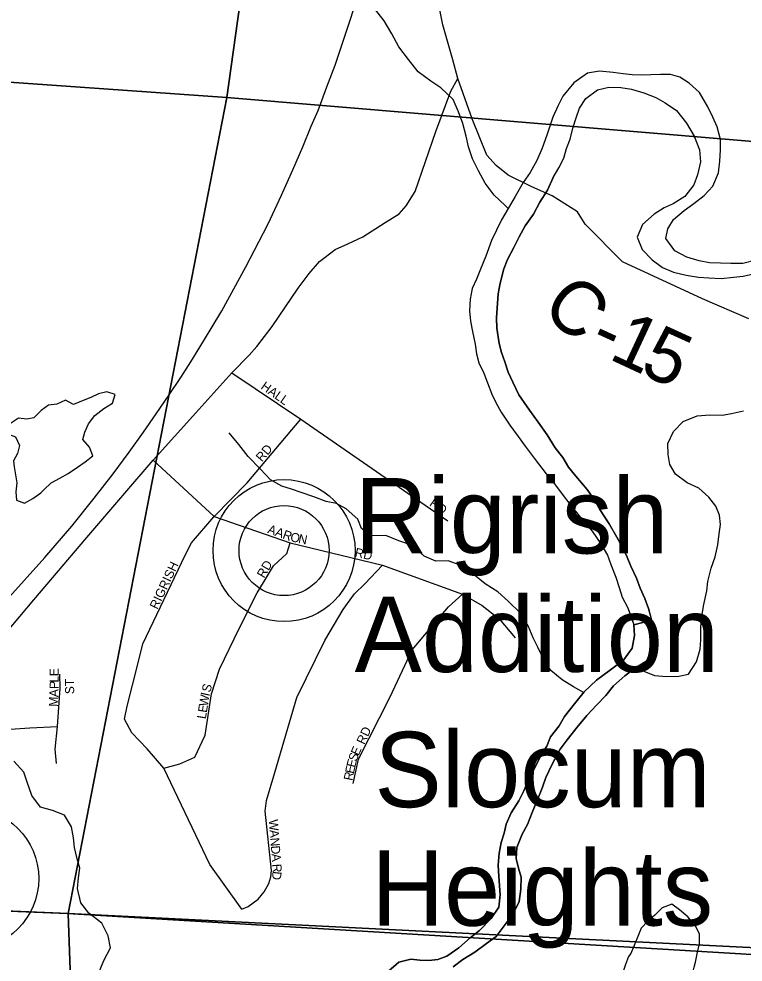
# Model space of a CAD drawing. Extents: x 1624196 to 2029251, y 146837 to 440034.
# Drawn here: x 1865984 to 1869991, y 281306 to 286524 of the extents above; entities that cross this region are included whole.
import ezdxf

# ---------------------------------------------------------------- set-up
doc = ezdxf.new("R2010")
doc.units = 0
for name, color, linetype in [('GM_X_County_Road', 7, 'Continuous'), ('GM_X_County_Road_Text', 7, 'Continuous'), ('GM_X_Major_River', 7, 'Continuous'), ('GM_X_Minor_Lake', 7, 'Continuous'), ('GM_X_Minor_River', 7, 'Continuous'), ('GM_X_Rail_Line', 7, 'Continuous'), ('GM_X_Section', 7, 'Continuous'), ('GM_X_State_Route', 7, 'Continuous'), ('GM_X_Township', 7, 'Continuous'), ('GM_X_Township_Subdivision', 7, 'Continuous'), ('GM_X_Township_Subdivision_Text', 7, 'Continuous'), ('GM_X_Unincorporated', 7, 'Continuous'), ('GM_X_Unincorporated_Location', 7, 'Continuous'), ('GM_X_Unincorporated_Text', 7, 'Continuous')]:
    doc.layers.add(name, color=color, linetype=linetype)

msp = doc.modelspace()

# ---------------------------------------------------------------- linework, layer by layer
at = {"layer": 'GM_X_County_Road'}
msp.add_lwpolyline([(1870021.8, 284865), (1869766.6, 284976), (1869323.4, 285180.8), (1869117.6, 285388.1), (1869074.6, 285456.5), (1868934.4, 285545.2), (1868821, 285594.7), (1868691.1, 285658.7), (1868625.1, 285712.3), (1868573.5, 285770.1), (1868492.6, 285971.2), (1868413.2, 286195)], dxfattribs=at)
at = {"layer": 'GM_X_Major_River'}
for p, q in [((1869485.1, 283197.2), (1869386.3, 283172.7)), ((1869386.3, 283172.7), (1869485.1, 283197.2))]:
    msp.add_line(p, q, dxfattribs=at)
for points in [[(1870060.6, 285189), (1869988.4, 285171.5), (1869922.3, 285170), (1869866.2, 285172.4), (1869804.2, 285174.9), (1869748.2, 285185.3), (1869678.3, 285205.8), (1869612.4, 285240.4), (1869562.9, 285308.8), (1869573.2, 285362.8), (1869605.6, 285414.7), (1869664, 285464.3), (1869718.3, 285501.9), (1869774.7, 285547.6), (1869823.1, 285599.3), (1869853.6, 285673.1), (1869862.1, 285737.2), (1869864.5, 285799.2), (1869864.9, 285857.3), (1869847.4, 285927.5), (1869823.7, 285979.8), (1869796.1, 286038.1), (1869748.5, 286116.5), (1869692.8, 286169), (1869641, 286201.4), (1869589.1, 286215.8), (1869533, 286216.3), (1869480.9, 286214.6), (1869430.9, 286213), (1869376.8, 286215.4), (1869326.8, 286219.8), (1869270.8, 286228.2), (1869196.8, 286234.8), (1869130.6, 286223.3), (1869054.2, 286169.8), (1868993.6, 286096.1), (1868967.2, 286044.2), (1868938.8, 285980.4), (1868904.1, 285880.5), (1868879.6, 285808.6), (1868849.1, 285740.7), (1868812.6, 285674.9), (1868774.1, 285619.1), (1868729.6, 285541.4), (1868691.1, 285475.6), (1868654.6, 285411.8), (1868626.2, 285355.9), (1868597.8, 285298), (1868567.2, 285212.1), (1868538.6, 285140.3), (1868516.2, 285084.3), (1868491.9, 285032.5), (1868481.5, 284974.5), (1868477, 284908.4), (1868482.6, 284852.3), (1868494.3, 284794.1), (1868507.8, 284723.9), (1868515.4, 284671.8), (1868529.1, 284621.6), (1868556.7, 284563.4), (1868576.4, 284511.1), (1868600, 284448.9), (1868623.7, 284398.6), (1868651.4, 284348.4), (1868700.9, 284275.9), (1868746.6, 284213.5), (1868784.2, 284161.1), (1868833.8, 284094.7), (1868901.3, 284008.1), (1868947, 283951.7), (1868994.6, 283887.2), (1869044.2, 283822.8), (1869107.8, 283746.2), (1869155.4, 283689.8), (1869203, 283619.3), (1869240.6, 283557), (1869258.3, 283506.8), (1869285.8, 283436.5), (1869305.5, 283378.2), (1869321.1, 283326), (1869352.4, 283266.6), (1869386.3, 283172.7)], [(1870060.6, 285189), (1869988.4, 285171.5), (1869922.3, 285170), (1869866.2, 285172.4), (1869804.2, 285174.9), (1869748.2, 285185.3), (1869678.3, 285205.8), (1869612.4, 285240.4), (1869562.9, 285308.8), (1869573.2, 285362.8), (1869605.6, 285414.7), (1869664, 285464.3), (1869718.3, 285501.9), (1869774.7, 285547.6), (1869823.1, 285599.3), (1869853.6, 285673.1), (1869862.1, 285737.2), (1869864.5, 285799.2), (1869864.9, 285857.3), (1869847.4, 285927.5), (1869823.7, 285979.8), (1869796.1, 286038.1), (1869748.5, 286116.5), (1869692.8, 286169), (1869641, 286201.4), (1869589.1, 286215.8), (1869533, 286216.3), (1869480.9, 286214.6), (1869430.9, 286213), (1869376.8, 286215.4), (1869326.8, 286219.8), (1869270.8, 286228.2), (1869196.8, 286234.8), (1869130.6, 286223.3), (1869054.2, 286169.8), (1868993.6, 286096.1), (1868967.2, 286044.2), (1868938.8, 285980.4), (1868904.1, 285880.5), (1868879.6, 285808.6), (1868849.1, 285740.7), (1868812.6, 285674.9), (1868774.1, 285619.1), (1868729.6, 285541.4), (1868691.1, 285475.6), (1868654.6, 285411.8), (1868626.2, 285355.9), (1868597.8, 285298), (1868567.2, 285212.1), (1868538.6, 285140.3), (1868516.2, 285084.3), (1868491.9, 285032.5), (1868481.5, 284974.5), (1868477, 284908.4), (1868482.6, 284852.3), (1868494.3, 284794.1), (1868507.8, 284723.9), (1868515.4, 284671.8), (1868529.1, 284621.6), (1868556.7, 284563.4), (1868576.4, 284511.1), (1868600, 284448.9), (1868623.7, 284398.6), (1868651.4, 284348.4), (1868700.9, 284275.9), (1868746.6, 284213.5), (1868784.2, 284161.1), (1868833.8, 284094.7), (1868901.3, 284008.1), (1868947, 283951.7), (1868994.6, 283887.2), (1869044.2, 283822.8), (1869107.8, 283746.2), (1869155.4, 283689.8), (1869203, 283619.3), (1869240.6, 283557), (1869258.3, 283506.8), (1869285.8, 283436.5), (1869305.5, 283378.2), (1869321.1, 283326), (1869352.4, 283266.6), (1869386.3, 283173.4)], [(1868940.5, 285645.9), (1868970.9, 285699.8), (1868999.3, 285753.6), (1869013.7, 285807.6), (1869034.1, 285859.5), (1869048.5, 285919.5), (1869066.9, 285977.4), (1869085.3, 286029.4), (1869119.7, 286083.2), (1869184.1, 286130.8), (1869248.2, 286146.3), (1869314.3, 286143.8), (1869372.3, 286135.3), (1869442.2, 286114.8), (1869508.1, 286088.3), (1869560, 286059.8), (1869621.7, 286017.3), (1869677.3, 285946.8), (1869718.9, 285874.4), (1869748.4, 285800.1), (1869753.9, 285734), (1869737.4, 285662), (1869717, 285606.1), (1869668.6, 285542.4), (1869604.2, 285500.8), (1869554, 285479.1), (1869497.7, 285443.5), (1869433.2, 285385.9), (1869404.7, 285316), (1869432.3, 285247.7), (1869488, 285191.2), (1869543.7, 285148.8), (1869605.6, 285122.3), (1869675.6, 285105.7), (1869743.6, 285095.2), (1869801.6, 285090.8), (1869869.7, 285088.3), (1869937.8, 285095.8), (1869989.9, 285101.4), (1870072.1, 285118.8)], [(1868940.5, 285645.9), (1868908, 285576.1), (1868865.5, 285510.3), (1868831, 285444.5), (1868784.5, 285378.7), (1868752.1, 285318.9), (1868721.6, 285259), (1868687.2, 285193.2), (1868666.8, 285141.3), (1868646.2, 285061.3), (1868635.8, 285003.3), (1868629.3, 284923.3), (1868626.9, 284871.2), (1868628.5, 284813.2), (1868642, 284729), (1868653.6, 284678.8), (1868673.3, 284626.6), (1868690.9, 284570.4), (1868716.6, 284514.1), (1868750.1, 284443.8), (1868809.6, 284359.2), (1868857.2, 284292.8), (1868906.8, 284222.3), (1868950.4, 284151.9), (1868994, 284097.5), (1869023.7, 284045.2), (1869065.4, 283994.8), (1869127, 283920.3), (1869170.6, 283859.9), (1869198.3, 283809.6), (1869249.8, 283731.1), (1869291.3, 283656.7), (1869321, 283604.4), (1869348.6, 283546.1), (1869370.3, 283495.9), (1869399.9, 283429.6), (1869421.6, 283375.4), (1869447.2, 283317.1), (1869466.8, 283262.9), (1869486.4, 283192.6), (1869500, 283142.5), (1869511.7, 283086.3), (1869509.3, 283030.2), (1869458.8, 282972.5), (1869390.5, 282931), (1869336.1, 282889.4), (1869273.7, 282833.8), (1869231.3, 282782), (1869178.9, 282728.3), (1869126.4, 282670.6), (1869072, 282607), (1869017.4, 282535.3), (1868979, 282483.5), (1868934.4, 282401.7), (1868899.9, 282327.9), (1868881.5, 282274), (1868859.1, 282218), (1868824.5, 282134.2), (1868798, 282068.3), (1868767.6, 282014.5), (1868739.1, 281940.6), (1868734.7, 281880.5), (1868748.3, 281826.3), (1868762, 281776.2), (1868761.5, 281710.1), (1868751.1, 281642.1), (1868718.6, 281574.2), (1868664, 281500.6), (1868623.6, 281448.8), (1868571.3, 281409.1), (1868506.9, 281361.5), (1868440.6, 281320), (1868386.2, 281280.3)], [(1869485.1, 283197.2), (1869466.8, 283262.9), (1869447.2, 283317.1), (1869421.6, 283375.4), (1869399.9, 283429.6), (1869370.3, 283495.9), (1869348.6, 283546.1), (1869321, 283604.4), (1869291.3, 283656.7), (1869249.8, 283731.1), (1869198.3, 283809.6), (1869170.6, 283859.9), (1869127, 283920.3), (1869065.4, 283994.8), (1869023.7, 284045.2), (1868994, 284097.5), (1868950.4, 284151.9), (1868906.8, 284222.3), (1868857.2, 284292.8), (1868809.6, 284359.2), (1868750.1, 284443.8), (1868716.6, 284514.1), (1868690.9, 284570.4), (1868673.3, 284626.6), (1868653.6, 284678.8), (1868642, 284729), (1868628.5, 284813.2), (1868626.9, 284871.2), (1868629.3, 284923.3), (1868635.8, 285003.3), (1868646.2, 285061.3), (1868666.8, 285141.3), (1868687.2, 285193.2), (1868721.6, 285259), (1868752.1, 285318.9), (1868784.5, 285378.7), (1868831, 285444.5), (1868865.5, 285510.3), (1868908, 285576.1), (1868940.5, 285645.9)], [(1868029.2, 281256.7), (1868085.5, 281306.6), (1868151.7, 281322.3), (1868201.8, 281318.1), (1868251.8, 281315.8), (1868301.9, 281321.6), (1868352.1, 281339.5), (1868418.4, 281385.3), (1868480.7, 281441.1), (1868533, 281481), (1868597.4, 281546.8), (1868639.7, 281610.8), (1868646, 281678.9), (1868638.5, 281779.2), (1868634.8, 281843.4), (1868641.1, 281909.5), (1868651.3, 281967.6), (1868669.6, 282019.7), (1868679.8, 282069.8), (1868708.1, 282131.8), (1868750.5, 282197.8), (1868776.8, 282253.8), (1868807.1, 282323.8), (1868837.4, 282377.8), (1868871.8, 282449.8), (1868904.1, 282501.8), (1868924.3, 282551.8), (1868972.7, 282613.8), (1869003, 282665.8), (1869057.3, 282735.7), (1869111.7, 282801.6), (1869180.1, 282865.5), (1869256.5, 282923.2), (1869328.8, 282977), (1869377.2, 283043), (1869389.5, 283113.1), (1869386.3, 283173.4)], [(1869386.3, 283172.7), (1869389.5, 283113.1), (1869377.2, 283043), (1869328.8, 282977), (1869256.5, 282923.2), (1869180.1, 282865.5), (1869111.7, 282801.6), (1869057.3, 282735.7), (1869003, 282665.8), (1868972.7, 282613.8), (1868924.3, 282551.8), (1868904.1, 282501.8), (1868871.8, 282449.8), (1868837.4, 282377.8), (1868807.1, 282323.8), (1868776.8, 282253.8), (1868750.5, 282197.8), (1868708.1, 282131.8), (1868679.8, 282069.8), (1868669.6, 282019.7), (1868651.3, 281967.6), (1868641.1, 281909.5), (1868634.8, 281843.4), (1868638.5, 281779.2), (1868646, 281678.9), (1868639.7, 281610.8), (1868597.4, 281546.8), (1868533, 281481), (1868480.7, 281441.1), (1868418.4, 281385.3), (1868352.1, 281339.5), (1868301.9, 281321.6), (1868251.8, 281315.8), (1868201.8, 281318.1), (1868151.7, 281322.3), (1868085.5, 281306.6), (1868029.2, 281256.7)], [(1868386.2, 281280.3), (1868440.6, 281320), (1868506.9, 281361.5), (1868571.3, 281409.1), (1868623.6, 281448.8), (1868664, 281500.6), (1868718.6, 281574.2), (1868751.1, 281642.1), (1868761.5, 281710.1), (1868762, 281776.2), (1868748.3, 281826.3), (1868734.7, 281880.5), (1868739.1, 281940.6), (1868767.6, 282014.5), (1868798, 282068.3), (1868824.5, 282134.2), (1868859.1, 282218), (1868881.5, 282274), (1868899.9, 282327.9), (1868934.4, 282401.7), (1868979, 282483.5), (1869017.4, 282535.3), (1869072, 282607), (1869126.4, 282670.6), (1869178.9, 282728.3), (1869231.3, 282782), (1869273.7, 282833.8), (1869336.1, 282889.4), (1869390.5, 282931), (1869458.8, 282972.5), (1869509.3, 283030.2), (1869511.7, 283086.3), (1869500, 283142.5), (1869485.1, 283197.2)]]:
    msp.add_lwpolyline(points, dxfattribs=at)
at = {"layer": 'GM_X_Minor_Lake'}
for points in [[(1866122.1, 283918.3), (1866162.3, 283958.2), (1866210.5, 283984.1), (1866256.7, 284009.9), (1866309, 284043.8), (1866351.1, 284073.7), (1866393.4, 284107.5), (1866375.5, 284155.8), (1866337.7, 284198), (1866349.9, 284238.1), (1866370.1, 284284.1), (1866404.4, 284330.1), (1866454.6, 284367.9), (1866502.8, 284397.8), (1866517, 284445.8), (1866471, 284460.1), (1866424.9, 284450.3), (1866382.8, 284430.4), (1866330.6, 284408.6), (1866286.4, 284390.8), (1866242.5, 284415), (1866194.3, 284393.2), (1866148.2, 284387.4), (1866108, 284357.5), (1866087, 284336.6)], [(1866087, 284336.6), (1866067.8, 284317.6), (1866027.7, 284309.8), (1865981.7, 284316), (1865933.4, 284282.1), (1865913.2, 284232.1), (1865965.2, 284211.8), (1865987, 284163.6), (1865976.8, 284119.5), (1865954.6, 284079.5), (1865958.4, 284045.4), (1865974, 283957.1), (1865967.8, 283907), (1865971.6, 283860.9), (1866015.6, 283844.6), (1866061.8, 283870.5), (1866106, 283902.4), (1866122.1, 283918.3)], [(1869720.3, 281279.2), (1869728, 281307), (1869738.3, 281361.1), (1869748.5, 281407.1), (1869748.8, 281461.3), (1869726.9, 281507.5), (1869685.1, 281557.8), (1869639.2, 281596.1), (1869595.3, 281626.4), (1869543.1, 281606.6), (1869502.9, 281566.7), (1869462.6, 281532.8), (1869426.4, 281494.8), (1869408.2, 281448.8), (1869392, 281406.8), (1869369.7, 281354.8), (1869355.6, 281336.8)], [(1869355.6, 281336.8), (1869339.4, 281292.7), (1869325.2, 281248.7), (1869300.9, 281200.7), (1869272.7, 281154.7), (1869224.4, 281108.8), (1869234.2, 281062.6), (1869284.2, 281042.4), (1869332.3, 281038.1), (1869388.3, 281039.9), (1869418.4, 281041.7), (1869462.5, 281043.5), (1869510.6, 281051.3), (1869556.7, 281053.1), (1869586.8, 281069), (1869627, 281102.9), (1869663.2, 281144.9), (1869691.5, 281188.8), (1869703.6, 281220.9), (1869715.8, 281262.9), (1869720.3, 281279.2)]]:
    msp.add_lwpolyline(points, dxfattribs=at)
at = {"layer": 'GM_X_Minor_River'}
for points in [[(1868690.8, 285475.1), (1868675, 285492.5), (1868613.1, 285548.9), (1868563.4, 285615.3), (1868527.6, 285683.6), (1868493.8, 285750), (1868472.1, 285816.2), (1868458.3, 285874.4), (1868440.6, 285944.7), (1868416.9, 286009), (1868387.1, 286077.3), (1868319.3, 286141.8), (1868263.4, 286180.1), (1868193.5, 286230.6), (1868139.7, 286299), (1868086, 286369.4), (1868048.2, 286441.8), (1868004.5, 286514.1), (1867950.7, 286580.6)], [(1869411.7, 282943.9), (1869432.7, 282920.4), (1869500.7, 282892), (1869566.8, 282885.7), (1869634.9, 282887.4), (1869689, 282899.2), (1869733.4, 282967.1), (1869753.8, 283037.2), (1869756, 283089.3), (1869756.3, 283159.5), (1869762.6, 283219.6), (1869772.9, 283283.8), (1869789.2, 283359.9), (1869795.5, 283412), (1869813.8, 283486.1), (1869836.1, 283548.1), (1869850.5, 283614.2), (1869858.7, 283676.4), (1869865, 283726.5), (1869859.2, 283778.6), (1869839.4, 283828.8), (1869801.5, 283879.1), (1869745.7, 283927.5), (1869681.7, 283957.9), (1869615.8, 284006.3), (1869586, 284058.6), (1869576.3, 284114.8), (1869574.5, 284174.9), (1869604.9, 284241), (1869659.2, 284296.8), (1869735.4, 284328.6), (1869805.6, 284334.3), (1869873.7, 284332), (1869925.8, 284341.7), (1869992, 284355.5)], [(1869108.3, 282797.5), (1869051.8, 282830), (1868989.8, 282868.3), (1868926, 282918.8), (1868892.1, 282971.1), (1868854.4, 283049.4), (1868828.6, 283099.7), (1868800.9, 283166), (1868759.1, 283236.3), (1868691.3, 283302.8), (1868633.4, 283355.2), (1868563.5, 283399.7), (1868495.7, 283454.1), (1868431.8, 283500.5), (1868359.8, 283526.9), (1868291.7, 283525.2), (1868225.7, 283551.6), (1868161.9, 283610.1), (1868085.9, 283636.5), (1868013.9, 283666.9), (1867933.8, 283665.3), (1867879.8, 283705.6), (1867860, 283755.8), (1867794.2, 283814.3), (1867742.2, 283842.6), (1867684.2, 283854.9), (1867616.2, 283879.3), (1867546.2, 283903.7), (1867492.2, 283922), (1867438.2, 283938.3), (1867376.3, 283974.6), (1867320.4, 284033), (1867252.7, 284103.5), (1867200.9, 284170), (1867147.1, 284234.4)], [(1866414.5, 281104.6), (1866414.3, 281148), (1866418.5, 281200.1), (1866434.8, 281266.2), (1866455.1, 281316.2), (1866491.5, 281386.2), (1866477.7, 281452.5), (1866444, 281522.8), (1866372.1, 281577.2), (1866326.3, 281633.6), (1866308.6, 281713.9), (1866314.9, 281772), (1866321.1, 281826.1), (1866307.4, 281878.3), (1866291.6, 281940.5), (1866285.8, 281994.7), (1866276.1, 282054.9), (1866236.3, 282119.3), (1866170.3, 282145.6), (1866104.3, 282164), (1866056.5, 282228.4), (1866028.8, 282306.7), (1866011, 282356.9), (1865957.2, 282417.3)]]:
    msp.add_lwpolyline(points, dxfattribs=at)
at = {"layer": 'GM_X_Rail_Line'}
msp.add_lwpolyline([(1865916, 283309.1), (1866128.3, 283544.7), (1866276.6, 283718.4), (1866401.6, 283873.2), (1866505.6, 284008.2), (1866594.1, 284127.7), (1866673.7, 284237.2), (1866743.4, 284339), (1866816.4, 284444.1), (1866879.5, 284540.3), (1866934.8, 284626.6), (1866985.7, 284707.3), (1867047.6, 284811.3), (1867106.3, 284909.8), (1867240.1, 285153.1), (1867312, 285291.4), (1867362.9, 285391), (1867437, 285548.1), (1867500.1, 285689.7), (1867555.4, 285815.8), (1867601.8, 285929.7), (1867639.5, 286017.1), (1867688.1, 286147.6), (1867733.5, 286268.2), (1867774.4, 286389.9), (1867809.8, 286493.9), (1867841.9, 286596.8)], dxfattribs=at)
at = {"layer": 'GM_X_Section'}
for points in [[(1862824.6, 291929.6), (1867901.8, 291578.2), (1867134.9, 286088.4), (1862319.7, 286429), (1862431.2, 289184.8)], [(1867901.8, 291578.2), (1873797.2, 291263.9), (1873309.6, 285573.1), (1867134.9, 286088.4)], [(1862319.7, 286429), (1867134.9, 286088.4), (1866257.2, 281575.1), (1862193.5, 281747.1)], [(1867134.9, 286088.4), (1873309.6, 285573.1), (1872946.7, 281242), (1866257.2, 281575.1)], [(1862193.5, 281747.1), (1866257.2, 281575.1), (1866452.3, 276073.9), (1861882.7, 276297.8)], [(1866257.2, 281575.1), (1872946.7, 281242), (1872577.6, 275738.7), (1866452.3, 276073.9)]]:
    msp.add_lwpolyline(points, close=True, dxfattribs=at)
at = {"layer": 'GM_X_State_Route'}
for points in [[(1868384.4, 286297), (1868329.7, 286491), (1868303.4, 286619.9), (1868295.1, 286685.9), (1868345.5, 287067.5), (1868383, 287719.5), (1868402.3, 287923.2), (1868434.9, 288286.9), (1868461.1, 288384.9), (1868499.5, 288460.1), (1868533.4, 288531.3), (1868588.3, 288641.7), (1868628.2, 288729.5)], [(1865911.8, 283125.9), (1866066.8, 283310.8), (1866361.1, 283655), (1866560.2, 283886.9), (1866726.6, 284083.2), (1866964, 284344.9), (1867163.1, 284566.8), (1867257.8, 284663), (1867300.9, 284712.1), (1867385.9, 284822.3), (1867528.4, 285034.3), (1867589.5, 285115.7), (1867647, 285181.6), (1867733.2, 285247.5), (1867803.9, 285280.5), (1867887.1, 285318.8), (1868009.7, 285397.2), (1868088.8, 285445.1), (1868127.1, 285490.6), (1868175.6, 285570), (1868291.5, 285901), (1868374, 286124.9), (1868413.2, 286195), (1868384.4, 286297)]]:
    msp.add_lwpolyline(points, dxfattribs=at)
at = {"layer": 'GM_X_Township'}
for points in [[(1870622.5, 281312.7), (1866253.5, 281574.5), (1865748.3, 281595.7), (1865271, 281604.8), (1863363.2, 281640.8), (1863077.8, 281653.7), (1862899, 281661.8), (1862618.4, 281674.4), (1862405.5, 281684.1), (1862209.2, 281692.9), (1862158, 281695.2), (1861836.7, 281721.8), (1861583.6, 281742.7), (1861130, 281764.3), (1860481.9, 281795.1), (1857692.6, 281927.6), (1857659.7, 281928.5), (1856919.6, 281947.1), (1856659.2, 281953.7), (1855546, 281981.8), (1851664.4, 282062.3), (1851666.7, 282683.6), (1851668.9, 283289.1), (1851682.9, 287150.5)], [(1851682.9, 287150.5), (1851668.9, 283289.1), (1851666.7, 282683.6), (1851664.4, 282062.3), (1855546, 281981.8), (1856659.2, 281953.7), (1856919.6, 281947.1), (1857659.7, 281928.5), (1857692.6, 281927.6), (1860481.9, 281795.1), (1861130, 281764.3), (1861583.6, 281742.7), (1861836.7, 281721.8), (1862158, 281695.2), (1862209.2, 281692.9), (1862405.5, 281684.1), (1862618.4, 281674.4), (1862899, 281661.8), (1863077.8, 281653.7), (1863363.2, 281640.8), (1865271, 281604.8), (1865748.3, 281595.7), (1866253.5, 281574.5), (1870622.5, 281312.7)]]:
    msp.add_lwpolyline(points, dxfattribs=at)
at = {"layer": 'GM_X_Township_Subdivision'}
for points in [[(1867163.1, 284566.8), (1867543.6, 284310.2), (1868357.9, 283748.3)], [(1867062.1, 283770.1), (1867063.9, 283772.2), (1867247, 283958), (1867543.6, 284310.2)], [(1866726.6, 284083.2), (1867063.9, 283772.2), (1867485.9, 283625.2), (1867995.3, 283502.1), (1868439.2, 283342.2), (1868547.9, 283279.3), (1868641.2, 283205.8), (1868728.7, 283100.2)], [(1867217.7, 281599.7), (1867040.4, 281846.8), (1866785.5, 282379.8), (1866693.9, 282485.8), (1866608.5, 282574), (1866568.7, 282650.8), (1866582.9, 282721.9), (1866642.7, 282953.8), (1866669.7, 283067.6), (1866904.3, 283556.9), (1866938.4, 283625.2), (1867062.1, 283770.1)], [(1866785.5, 282379.8), (1866875.2, 282402.6), (1866958.3, 282440.3), (1867015.2, 282562.6), (1867049.3, 282790.2), (1867094.8, 282926.8), (1867202.1, 283152.6), (1867303, 283349.9), (1867338.1, 283405.7), (1867393.4, 283498.5), (1867467.4, 283566.8), (1867485.9, 283625.2)], [(1867217.7, 281599.7), (1867251.9, 281613.3), (1867308.7, 281654.7), (1867342.1, 281695.7), (1867366.6, 281740.6), (1867378.5, 281778.1), (1867380.9, 281814), (1867347.2, 282141.7), (1867354.3, 282199.7), (1867400.2, 282355.6), (1867522, 282769.3), (1867676.7, 283086.1), (1867777.3, 283257.3), (1867840.6, 283342.8), (1867897.5, 283398.2), (1867995.3, 283502.1)], [(1867832.8, 282293.7), (1867862.6, 282429.8), (1868037.7, 282774.5), (1868159.5, 283033.7), (1868361.3, 283271.7), (1868439.2, 283342.2)], [(1866193.3, 282404.3), (1866185.4, 282484.5), (1866197.9, 282610.1), (1866213, 282821.1), (1866211.7, 282900)], [(1865721.2, 282621), (1865852.9, 282589.7), (1866044.8, 282601.5), (1866197.9, 282610.1)]]:
    msp.add_lwpolyline(points, dxfattribs=at)
at = {"layer": 'GM_X_Unincorporated'}
for centre, radius in [((1867451.1, 283582.9), 392.8), ((1867451.1, 283582.9), 249), ((1865701.6, 281768.4), 392.8)]:
    msp.add_circle(centre, radius, dxfattribs=at)
at = {"layer": 'GM_X_Unincorporated_Location'}
msp.add_line((1867451.1, 283582.9), (1867451.1, 283582.9), dxfattribs=at)

# ---------------------------------------------------------------- texts
at = {"layer": 'GM_X_County_Road_Text'}
for s, rotation, p in [('C', 318.9885, (1868864.3, 284909.8)), ('1', 335.0526, (1869240, 284646.4)), ('-', 335.3233, (1869128.4, 284697.6)), ('5', 335.4792, (1869409.8, 284567.4))]:
    msp.add_text(s, height=300, rotation=rotation, dxfattribs=at).set_placement(p)
at = {"layer": 'GM_X_Township_Subdivision_Text'}
for s, rotation, p in [('HALL', 325.007, (1867318.6, 284480.8)), ('RD', 49.3961, (1867328.4, 284070.5)), ('RD', 325.495, (1868251.3, 283834)), ('A', 339.9478, (1867356.4, 283681.6)), ('A', 339.9693, (1867397.8, 283666.5)), ('R', 340.4486, (1867439.5, 283651.3)), ('O', 346.3636, (1867482.3, 283636.5)), ('N', 348.6687, (1867527.2, 283625.6)), ('RD', 347.4648, (1867839.2, 283550)), ('RIGRISH', 64.798, (1866750.6, 283254.4)), ('RD', 59.5361, (1867340.7, 283426.8)), ('E', 89.9956, (1866204.2, 282887.9)), ('P', 89.3679, (1866203.8, 282816.9)), ('L', 89.9639, (1866204.1, 282852.6)), ('ST', 90, (1866290.2, 282788.4)), ('A', 87.786, (1866202, 282771.4)), ('S', 74.5124, (1867042.5, 282795.1)), ('M', 87.5405, (1866199.8, 282718.4)), ('W', 80.9841, (1867029.2, 282718.6)), ('I', 77.7129, (1867038, 282774.3)), ('E', 81.0426, (1867023.7, 282683.8)), ('L', 81.0295, (1867018.3, 282649)), ('RD', 64.8007, (1867894.7, 282506.4)), ('E', 65.9231, (1867863.5, 282445.1)), ('S', 70.8776, (1867852.3, 282412.9)), ('E', 78.3094, (1867837.1, 282345.9)), ('E', 75.8321, (1867844.1, 282379.8)), ('R', 78.3094, (1867829, 282307.1)), ('W', 274.4767, (1867366.9, 282094)), ('A', 274.4908, (1867371.4, 282036.9)), ('N', 274.485, (1867374.8, 281993.1)), ('D', 274.4632, (1867378.3, 281949.2)), ('A', 274.4908, (1867381.7, 281905.3)), ('R', 273.5968, (1867386.2, 281848.5)), ('D', 263.7588, (1867388.7, 281811.2))]:
    msp.add_text(s, height=50, rotation=rotation, dxfattribs=at).set_placement(p)
at = {"layer": 'GM_X_Unincorporated_Text'}
for s, p in [('Rigrish', (1867841.6, 283567)), ('Addition', (1867841.6, 282911.4)), ('Slocum', (1867951.6, 282163.4)), ('Heights', (1867934, 281507.8))]:
    msp.add_text(s, height=417, rotation=0, dxfattribs=at).set_placement(p)

doc.saveas('drawing.dxf')
